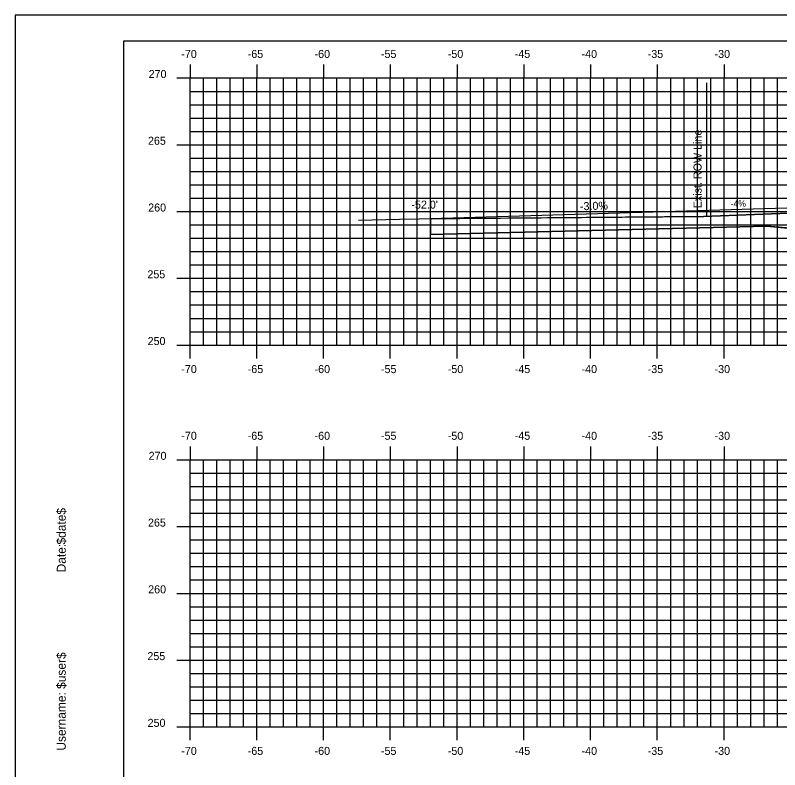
# Model space of a CAD drawing. Extents: x 856235 to 856405, y 366268 to 366378.
# Drawn here: x 856234.7 to 856291.9, y 366321.7 to 366378.2 of the extents above; entities that cross this region are included whole.
import ezdxf

# ---------------------------------------------------------------- set-up
doc = ezdxf.new("R2010")
doc.units = 0
for name, color, linetype in [('BORDER', 7, 'Continuous'), ('D_Roadway_Drive_Gravel_LT', 7, 'Continuous'), ('D_Roadway_Drive_SubGrade', 7, 'Continuous'), ('D_Text_Standard', 7, 'Continuous'), ('E_ROW_Line', 7, 'Continuous'), ('H_V ANNOTATION', 7, 'Continuous'), ('JUNK COM EXC', 7, 'Continuous'), ('MAJOR', 7, 'Continuous'), ('MINOR', 7, 'Continuous'), ('PLOT BOUNDARY', 7, 'Continuous'), ('S_Roadway_Centerline', 7, 'Continuous')]:
    doc.layers.add(name, color=color, linetype=linetype)

msp = doc.modelspace()

# ---------------------------------------------------------------- linework, layer by layer
at = {"layer": 'BORDER'}
for p, q in [((856402.781, 366376.236), (856242.781, 366376.236)), ((856242.781, 366376.236), (856242.781, 366271.236))]:
    msp.add_line(p, q, dxfattribs=at)
at = {"layer": 'D_Roadway_Drive_Gravel_LT'}
for p, q in [((856296.981, 366363.872), (856265.781, 366362.934)), ((856290.981, 366362.395), (856265.781, 366361.768))]:
    msp.add_line(p, q, dxfattribs=at)
at = {"layer": 'D_Roadway_Drive_SubGrade'}
for p, q in [((856265.781, 366362.934), (856265.781, 366361.768)), ((856300.981, 366361.439), (856290.981, 366362.395))]:
    msp.add_line(p, q, dxfattribs=at)
at = {"layer": 'E_ROW_Line'}
msp.add_line((856286.494, 366363.127), (856286.494, 366373.127), dxfattribs=at)
at = {"layer": 'JUNK COM EXC'}
msp.add_lwpolyline([(856300.981, 366363.404), (856300.702, 366363.394), (856300.563, 366363.43), (856296.348, 366363.536), (856294.317, 366363.378), (856292.601, 366363.365), (856286.23, 366363.117), (856265.781, 366362.934), (856265.781, 366361.768), (856290.981, 366362.395), (856300.981, 366361.439), (856306.781, 366361.571), (856317.781, 366361.791), (856328.781, 366361.571), (856337.781, 366361.391), (856337.781, 366364.18), (856340.197, 366364.228), (856343.261, 366365.249)], dxfattribs=at)
at = {"layer": 'MAJOR'}
for p, q in [((856247.781, 366374.483), (856247.781, 366373.481)), ((856252.781, 366374.483), (856252.781, 366373.481)), ((856257.781, 366374.483), (856257.781, 366373.481)), ((856262.781, 366374.483), (856262.781, 366373.481)), ((856267.781, 366374.483), (856267.781, 366373.481)), ((856272.781, 366374.483), (856272.781, 366373.481)), ((856277.781, 366374.483), (856277.781, 366373.481)), ((856282.781, 366374.483), (856282.781, 366373.481)), ((856287.781, 366374.483), (856287.781, 366373.481)), ((856246.779, 366373.481), (856247.781, 366373.481)), ((856247.781, 366373.481), (856387.781, 366373.481)), ((856247.781, 366353.481), (856247.781, 366373.481)), ((856247.781, 366353.481), (856247.781, 366373.481)), ((856247.781, 366373.481), (856387.781, 366373.481)), ((856252.781, 366353.481), (856252.781, 366373.481)), ((856257.781, 366353.481), (856257.781, 366373.481)), ((856262.781, 366353.481), (856262.781, 366373.481)), ((856267.781, 366353.481), (856267.781, 366373.481)), ((856272.781, 366353.481), (856272.781, 366373.481)), ((856277.781, 366353.481), (856277.781, 366373.481)), ((856282.781, 366353.481), (856282.781, 366373.481)), ((856287.781, 366353.481), (856287.781, 366373.481)), ((856246.779, 366368.481), (856247.781, 366368.481)), ((856247.781, 366368.481), (856387.781, 366368.481)), ((856246.779, 366363.481), (856247.781, 366363.481)), ((856247.781, 366363.481), (856387.781, 366363.481)), ((856246.779, 366358.481), (856247.781, 366358.481)), ((856247.781, 366358.481), (856387.781, 366358.481)), ((856246.779, 366353.481), (856247.781, 366353.481)), ((856247.781, 366353.481), (856387.781, 366353.481)), ((856247.781, 366353.481), (856387.781, 366353.481)), ((856247.781, 366352.479), (856247.781, 366353.481)), ((856252.781, 366352.479), (856252.781, 366353.481)), ((856257.781, 366352.479), (856257.781, 366353.481)), ((856262.781, 366352.479), (856262.781, 366353.481)), ((856267.781, 366352.479), (856267.781, 366353.481)), ((856272.781, 366352.479), (856272.781, 366353.481)), ((856277.781, 366352.479), (856277.781, 366353.481)), ((856282.781, 366352.479), (856282.781, 366353.481)), ((856287.781, 366352.479), (856287.781, 366353.481)), ((856247.781, 366345.887), (856247.781, 366344.885)), ((856252.781, 366345.887), (856252.781, 366344.885)), ((856257.781, 366345.887), (856257.781, 366344.885)), ((856262.781, 366345.887), (856262.781, 366344.885)), ((856267.781, 366345.887), (856267.781, 366344.885)), ((856272.781, 366345.887), (856272.781, 366344.885)), ((856277.781, 366345.887), (856277.781, 366344.885)), ((856282.781, 366345.887), (856282.781, 366344.885)), ((856287.781, 366345.887), (856287.781, 366344.885)), ((856246.779, 366344.885), (856247.781, 366344.885)), ((856247.781, 366344.885), (856387.781, 366344.885)), ((856247.781, 366324.885), (856247.781, 366344.885)), ((856247.781, 366324.885), (856247.781, 366344.885)), ((856247.781, 366344.885), (856387.781, 366344.885)), ((856252.781, 366324.885), (856252.781, 366344.885)), ((856257.781, 366324.885), (856257.781, 366344.885)), ((856262.781, 366324.885), (856262.781, 366344.885)), ((856267.781, 366324.885), (856267.781, 366344.885)), ((856272.781, 366324.885), (856272.781, 366344.885)), ((856277.781, 366324.885), (856277.781, 366344.885)), ((856282.781, 366324.885), (856282.781, 366344.885)), ((856287.781, 366324.885), (856287.781, 366344.885)), ((856246.779, 366339.885), (856247.781, 366339.885)), ((856247.781, 366339.885), (856387.781, 366339.885)), ((856246.779, 366334.885), (856247.781, 366334.885)), ((856247.781, 366334.885), (856387.781, 366334.885)), ((856246.779, 366329.885), (856247.781, 366329.885)), ((856247.781, 366329.885), (856387.781, 366329.885)), ((856246.779, 366324.885), (856247.781, 366324.885)), ((856247.781, 366324.885), (856387.781, 366324.885)), ((856247.781, 366324.885), (856387.781, 366324.885)), ((856247.781, 366323.883), (856247.781, 366324.885)), ((856252.781, 366323.883), (856252.781, 366324.885)), ((856257.781, 366323.883), (856257.781, 366324.885)), ((856262.781, 366323.883), (856262.781, 366324.885)), ((856267.781, 366323.883), (856267.781, 366324.885)), ((856272.781, 366323.883), (856272.781, 366324.885)), ((856277.781, 366323.883), (856277.781, 366324.885)), ((856282.781, 366323.883), (856282.781, 366324.885)), ((856287.781, 366323.883), (856287.781, 366324.885))]:
    msp.add_line(p, q, dxfattribs=at)
at = {"layer": 'MINOR'}
for p, q in [((856248.781, 366353.481), (856248.781, 366373.481)), ((856249.781, 366353.481), (856249.781, 366373.481)), ((856250.781, 366353.481), (856250.781, 366373.481)), ((856251.781, 366353.481), (856251.781, 366373.481)), ((856253.781, 366353.481), (856253.781, 366373.481)), ((856254.781, 366353.481), (856254.781, 366373.481)), ((856255.781, 366353.481), (856255.781, 366373.481)), ((856256.781, 366353.481), (856256.781, 366373.481)), ((856258.781, 366353.481), (856258.781, 366373.481)), ((856259.781, 366353.481), (856259.781, 366373.481)), ((856260.781, 366353.481), (856260.781, 366373.481)), ((856261.781, 366353.481), (856261.781, 366373.481)), ((856263.781, 366353.481), (856263.781, 366373.481)), ((856264.781, 366353.481), (856264.781, 366373.481)), ((856265.781, 366353.481), (856265.781, 366373.481)), ((856266.781, 366353.481), (856266.781, 366373.481)), ((856268.781, 366353.481), (856268.781, 366373.481)), ((856269.781, 366353.481), (856269.781, 366373.481)), ((856270.781, 366353.481), (856270.781, 366373.481)), ((856271.781, 366353.481), (856271.781, 366373.481)), ((856273.781, 366353.481), (856273.781, 366373.481)), ((856274.781, 366353.481), (856274.781, 366373.481)), ((856275.781, 366353.481), (856275.781, 366373.481)), ((856276.781, 366353.481), (856276.781, 366373.481)), ((856278.781, 366353.481), (856278.781, 366373.481)), ((856279.781, 366353.481), (856279.781, 366373.481)), ((856280.781, 366353.481), (856280.781, 366373.481)), ((856281.781, 366353.481), (856281.781, 366373.481)), ((856283.781, 366353.481), (856283.781, 366373.481)), ((856284.781, 366353.481), (856284.781, 366373.481)), ((856285.781, 366353.481), (856285.781, 366373.481)), ((856286.781, 366353.481), (856286.781, 366373.481)), ((856288.781, 366353.481), (856288.781, 366373.481)), ((856289.781, 366353.481), (856289.781, 366373.481)), ((856290.781, 366353.481), (856290.781, 366373.481)), ((856291.781, 366353.481), (856291.781, 366373.481)), ((856247.781, 366372.481), (856387.781, 366372.481)), ((856247.781, 366372.481), (856248.783, 366372.481)), ((856247.781, 366371.481), (856387.781, 366371.481)), ((856247.781, 366371.481), (856248.783, 366371.481)), ((856247.781, 366370.481), (856387.781, 366370.481)), ((856247.781, 366370.481), (856248.783, 366370.481)), ((856247.781, 366369.481), (856387.781, 366369.481)), ((856247.781, 366369.481), (856248.783, 366369.481)), ((856247.781, 366367.481), (856387.781, 366367.481)), ((856247.781, 366367.481), (856248.783, 366367.481)), ((856247.781, 366366.481), (856387.781, 366366.481)), ((856247.781, 366366.481), (856248.783, 366366.481)), ((856247.781, 366365.481), (856387.781, 366365.481)), ((856247.781, 366365.481), (856248.783, 366365.481)), ((856247.781, 366364.481), (856387.781, 366364.481)), ((856247.781, 366364.481), (856248.783, 366364.481)), ((856247.781, 366362.481), (856387.781, 366362.481)), ((856247.781, 366362.481), (856248.783, 366362.481)), ((856247.781, 366361.481), (856387.781, 366361.481)), ((856247.781, 366361.481), (856248.783, 366361.481)), ((856247.781, 366360.481), (856387.781, 366360.481)), ((856247.781, 366360.481), (856248.783, 366360.481)), ((856247.781, 366359.481), (856387.781, 366359.481)), ((856247.781, 366359.481), (856248.783, 366359.481)), ((856247.781, 366357.481), (856387.781, 366357.481)), ((856247.781, 366357.481), (856248.783, 366357.481)), ((856247.781, 366356.481), (856387.781, 366356.481)), ((856247.781, 366356.481), (856248.783, 366356.481)), ((856247.781, 366355.481), (856387.781, 366355.481)), ((856247.781, 366355.481), (856248.783, 366355.481)), ((856247.781, 366354.481), (856387.781, 366354.481)), ((856247.781, 366354.481), (856248.783, 366354.481)), ((856248.781, 366324.885), (856248.781, 366344.885)), ((856249.781, 366324.885), (856249.781, 366344.885)), ((856250.781, 366324.885), (856250.781, 366344.885)), ((856251.781, 366324.885), (856251.781, 366344.885)), ((856253.781, 366324.885), (856253.781, 366344.885)), ((856254.781, 366324.885), (856254.781, 366344.885)), ((856255.781, 366324.885), (856255.781, 366344.885)), ((856256.781, 366324.885), (856256.781, 366344.885)), ((856258.781, 366324.885), (856258.781, 366344.885)), ((856259.781, 366324.885), (856259.781, 366344.885)), ((856260.781, 366324.885), (856260.781, 366344.885)), ((856261.781, 366324.885), (856261.781, 366344.885)), ((856263.781, 366324.885), (856263.781, 366344.885)), ((856264.781, 366324.885), (856264.781, 366344.885)), ((856265.781, 366324.885), (856265.781, 366344.885)), ((856266.781, 366324.885), (856266.781, 366344.885)), ((856268.781, 366324.885), (856268.781, 366344.885)), ((856269.781, 366324.885), (856269.781, 366344.885)), ((856270.781, 366324.885), (856270.781, 366344.885)), ((856271.781, 366324.885), (856271.781, 366344.885)), ((856273.781, 366324.885), (856273.781, 366344.885)), ((856274.781, 366324.885), (856274.781, 366344.885)), ((856275.781, 366324.885), (856275.781, 366344.885)), ((856276.781, 366324.885), (856276.781, 366344.885)), ((856278.781, 366324.885), (856278.781, 366344.885)), ((856279.781, 366324.885), (856279.781, 366344.885)), ((856280.781, 366324.885), (856280.781, 366344.885)), ((856281.781, 366324.885), (856281.781, 366344.885)), ((856283.781, 366324.885), (856283.781, 366344.885)), ((856284.781, 366324.885), (856284.781, 366344.885)), ((856285.781, 366324.885), (856285.781, 366344.885)), ((856286.781, 366324.885), (856286.781, 366344.885)), ((856288.781, 366324.885), (856288.781, 366344.885)), ((856289.781, 366324.885), (856289.781, 366344.885)), ((856290.781, 366324.885), (856290.781, 366344.885)), ((856291.781, 366324.885), (856291.781, 366344.885)), ((856247.781, 366343.885), (856387.781, 366343.885)), ((856247.781, 366343.885), (856248.783, 366343.885)), ((856247.781, 366342.885), (856387.781, 366342.885)), ((856247.781, 366342.885), (856248.783, 366342.885)), ((856247.781, 366341.885), (856387.781, 366341.885)), ((856247.781, 366341.885), (856248.783, 366341.885)), ((856247.781, 366340.885), (856387.781, 366340.885)), ((856247.781, 366340.885), (856248.783, 366340.885)), ((856247.781, 366338.885), (856387.781, 366338.885)), ((856247.781, 366338.885), (856248.783, 366338.885)), ((856247.781, 366337.885), (856387.781, 366337.885)), ((856247.781, 366337.885), (856248.783, 366337.885)), ((856247.781, 366336.885), (856387.781, 366336.885)), ((856247.781, 366336.885), (856248.783, 366336.885)), ((856247.781, 366335.885), (856387.781, 366335.885)), ((856247.781, 366335.885), (856248.783, 366335.885)), ((856247.781, 366333.885), (856387.781, 366333.885)), ((856247.781, 366333.885), (856248.783, 366333.885)), ((856247.781, 366332.885), (856387.781, 366332.885)), ((856247.781, 366332.885), (856248.783, 366332.885)), ((856247.781, 366331.885), (856387.781, 366331.885)), ((856247.781, 366331.885), (856248.783, 366331.885)), ((856247.781, 366330.885), (856387.781, 366330.885)), ((856247.781, 366330.885), (856248.783, 366330.885)), ((856247.781, 366328.885), (856387.781, 366328.885)), ((856247.781, 366328.885), (856248.783, 366328.885)), ((856247.781, 366327.885), (856387.781, 366327.885)), ((856247.781, 366327.885), (856248.783, 366327.885)), ((856247.781, 366326.885), (856387.781, 366326.885)), ((856247.781, 366326.885), (856248.783, 366326.885)), ((856247.781, 366325.885), (856387.781, 366325.885)), ((856247.781, 366325.885), (856248.783, 366325.885))]:
    msp.add_line(p, q, dxfattribs=at)
at = {"layer": 'PLOT BOUNDARY'}
msp.add_lwpolyline([(856234.688, 366268.177), (856404.688, 366268.177), (856404.688, 366378.177), (856234.688, 366378.177)], close=True, dxfattribs=at)
at = {"layer": 'S_Roadway_Centerline'}
msp.add_lwpolyline([(856260.387, 366362.844), (856263.467, 366362.905), (856264.953, 366362.927), (856286.23, 366363.117), (856292.601, 366363.365)], dxfattribs=at)

# ---------------------------------------------------------------- texts
at = {"layer": 'BORDER'}
for s, p in [('$date$', (856238.466, 366338.542)), ('Date:', (856238.466, 366336.453)), ('$user$', (856238.466, 366327.728)), ('Username:', (856238.466, 366323.104))]:
    msp.add_text(s, height=0.6696, rotation=90, dxfattribs=at).set_placement(p)
at = {"layer": 'D_Roadway_Drive_Gravel_LT'}
msp.add_text('-4%', height=0.48, dxfattribs=at).set_placement((856288.273, 366363.833))
at = {"layer": 'D_Text_Standard'}
msp.add_text("-52.0'", height=0.6, dxfattribs=at).set_placement((856264.359, 366363.697))
msp.add_text('-3.0%', height=0.6, rotation=1.7219, dxfattribs=at).set_placement((856276.994, 366363.572))
at = {"layer": 'E_ROW_Line'}
msp.add_text('Exist. ROW Line', height=0.6, rotation=90, dxfattribs=at).set_placement((856286.094, 366363.727))
at = {"layer": 'H_V ANNOTATION'}
for s, p in [('-70', (856247.122, 366374.981)), ('-65', (856252.098, 366374.981)), ('-60', (856257.106, 366374.981)), ('-55', (856262.077, 366374.981)), ('-50', (856267.085, 366374.981)), ('-45', (856272.098, 366374.981)), ('-40', (856277.106, 366374.981)), ('-35', (856282.061, 366374.981)), ('-30', (856287.069, 366374.981)), ('270', (856244.675, 366373.481)), ('265', (856244.627, 366368.481)), ('260', (856244.643, 366363.481)), ('255', (856244.584, 366358.481)), ('250', (856244.6, 366353.481)), ('-70', (856247.122, 366351.381)), ('-65', (856252.098, 366351.381)), ('-60', (856257.106, 366351.381)), ('-55', (856262.077, 366351.381)), ('-50', (856267.085, 366351.381)), ('-45', (856272.098, 366351.381)), ('-40', (856277.106, 366351.381)), ('-35', (856282.061, 366351.381)), ('-30', (856287.069, 366351.381)), ('-70', (856247.122, 366346.385)), ('-65', (856252.098, 366346.385)), ('-60', (856257.106, 366346.385)), ('-55', (856262.077, 366346.385)), ('-50', (856267.085, 366346.385)), ('-45', (856272.098, 366346.385)), ('-40', (856277.106, 366346.385)), ('-35', (856282.061, 366346.385)), ('-30', (856287.069, 366346.385)), ('270', (856244.675, 366344.885)), ('265', (856244.627, 366339.885)), ('260', (856244.643, 366334.885)), ('255', (856244.584, 366329.885)), ('250', (856244.6, 366324.885)), ('-70', (856247.122, 366322.785)), ('-65', (856252.098, 366322.785)), ('-60', (856257.106, 366322.785)), ('-55', (856262.077, 366322.785)), ('-50', (856267.085, 366322.785)), ('-45', (856272.098, 366322.785)), ('-40', (856277.106, 366322.785)), ('-35', (856282.061, 366322.785)), ('-30', (856287.069, 366322.785))]:
    msp.add_text(s, height=0.6, dxfattribs=at).set_placement(p)
at = {"layer": 'MAJOR'}
for p in [(856247.776, 366353.481), (856247.78, 366324.884)]:
    msp.add_text('-', height=0.00000006, rotation=53.1301, dxfattribs=at).set_placement(p)

doc.saveas('drawing.dxf')
